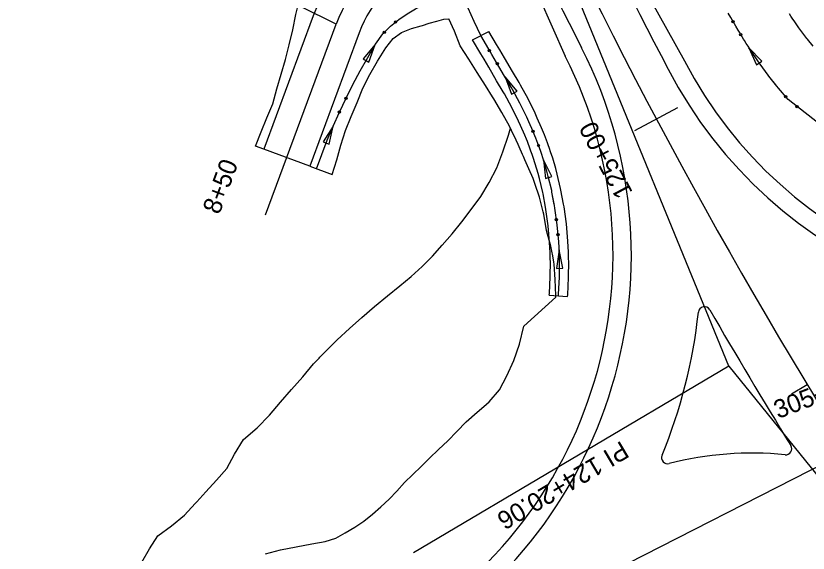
# Model space of a CAD drawing. Extents: x 916431 to 921570, y 1763982 to 1768032.
# Drawn here: x 918429.9 to 918689.4, y 1765529.8 to 1765705.9 of the extents above; entities that cross this region are included whole.
import ezdxf

# ---------------------------------------------------------------- set-up
doc = ezdxf.new("R2010")
doc.units = 0
for name, color, linetype in [('R_Conc Ditch Paving', 7, 'Continuous'), ('R_Horz Alg', 7, 'Continuous'), ('R_Horz Alg Annot', 7, 'Continuous'), ('R_Horz Alg Stationing', 7, 'Continuous'), ('R_Proposed Const Limits', 7, 'Continuous'), ('R_Proposed Road', 7, 'Continuous'), ('R_Shld', 7, 'Continuous'), ('R_Special Ditch', 7, 'Continuous')]:
    doc.layers.add(name, color=color, linetype=linetype)

msp = doc.modelspace()

# ---------------------------------------------------------------- linework, layer by layer
at = {"layer": 'R_Conc Ditch Paving'}
for p, q in [((918579.5, 1765697.99), (918584.83, 1765700.77)), ((918604.6, 1765614.37), (918610.58, 1765613.93))]:
    msp.add_line(p, q, dxfattribs=at)
for points in [[(918610.58, 1765613.93), (918610.63, 1765614.5), (918610.91, 1765620.14), (918610.95, 1765625.47), (918610.94, 1765626.18), (918610.88, 1765628.53), (918610.81, 1765630.12), (918610.7, 1765632.06), (918610.19, 1765637.75), (918609.43, 1765643.28), (918609.28, 1765644.19), (918608.43, 1765648.71), (918608.32, 1765649.24), (918607.19, 1765654.01), (918606.71, 1765655.79), (918605.71, 1765659.18), (918605.01, 1765661.35), (918604.64, 1765662.43), (918604.23, 1765663.59), (918604, 1765664.24), (918603.01, 1765666.83), (918602.68, 1765667.66), (918602.08, 1765669.14), (918600.67, 1765672.38), (918599.95, 1765673.95), (918597.65, 1765678.62), (918595.16, 1765683.19), (918594.72, 1765683.96), (918592.54, 1765687.66), (918589.94, 1765692.07), (918588.4, 1765694.68), (918587.34, 1765696.48), (918584.83, 1765700.77)], [(918604.6, 1765614.37), (918604.64, 1765614.88), (918604.91, 1765620.31), (918604.95, 1765625.45), (918604.94, 1765626.05), (918604.88, 1765628.32), (918604.82, 1765629.82), (918604.71, 1765631.62), (918604.23, 1765637.08), (918603.5, 1765642.39), (918603.38, 1765643.15), (918602.55, 1765647.53), (918602.46, 1765647.92), (918601.37, 1765652.53), (918600.93, 1765654.16), (918599.97, 1765657.41), (918599.31, 1765659.46), (918598.97, 1765660.46), (918598.58, 1765661.57), (918598.37, 1765662.15), (918597.42, 1765664.66), (918597.12, 1765665.42), (918596.55, 1765666.81), (918595.19, 1765669.94), (918594.53, 1765671.37), (918592.33, 1765675.86), (918589.93, 1765680.26), (918589.54, 1765680.94), (918587.37, 1765684.61), (918584.77, 1765689.02), (918583.23, 1765691.64), (918582.17, 1765693.44), (918579.5, 1765697.99)]]:
    msp.add_lwpolyline(points, dxfattribs=at)
at = {"layer": 'R_Horz Alg'}
for p, q in [((918511.69, 1765640.62), (918534.84, 1765703.08)), ((918519.58, 1765470.12), (918702.47, 1765563.28))]:
    msp.add_line(p, q, dxfattribs=at)
for centre, radius, start, end in [((920196.91, 1766498.5), 1762.95, 202.25028, 218.97694), ((918581.72, 1765685.7), 50, 115.128, 159.6685)]:
    msp.add_arc(centre, radius, start, end, dxfattribs=at)
at = {"layer": 'R_Horz Alg Annot'}
for q in [(918594.92, 1765758.39), (918777.08, 1765450.54)]:
    msp.add_line((918663.37, 1765591.08), q, dxfattribs=at)
for points in [[(918534.84, 1765703.08), (918418.4, 1765760.9)], [(918663.37, 1765591.08), (918560.09, 1765529.97)]]:
    msp.add_lwpolyline(points, dxfattribs=at)
at = {"layer": 'R_Horz Alg Stationing'}
for points in [[(918632.61, 1765668.31), (918646.74, 1765675.81)], [(918683.9, 1765581.99), (918689.03, 1765585.1)]]:
    msp.add_lwpolyline(points, dxfattribs=at)
at = {"layer": 'R_Proposed Const Limits'}
for points in [[(918514.09, 1765677.06), (918515.41, 1765681.9), (918516.85, 1765686.7), (918518.22, 1765691.52), (918519.47, 1765696.39), (918520.6, 1765701.31), (918521.6, 1765706.27), (918523.01, 1765712.12), (918525.2, 1765718.28), (918528.95, 1765723.6), (918533.35, 1765728.36), (918534.22, 1765729.16), (918538.32, 1765732.48), (918543.28, 1765736.48), (918548.72, 1765739.77), (918552.79, 1765742.46)], [(918691.02, 1765695.87), (918689.16, 1765698.2), (918688.96, 1765698.44), (918687.01, 1765701), (918686.32, 1765701.96), (918684.98, 1765703.88), (918684.14, 1765705.14), (918683.74, 1765705.77), (918683.29, 1765706.47)], [(918535.04, 1765658.63), (918536.3, 1765663.5), (918537.9, 1765668.24), (918539.75, 1765672.88), (918541.67, 1765677.51), (918543.52, 1765682.15), (918545.88, 1765686.61), (918548.38, 1765691.01), (918551.03, 1765695.37), (918553.5, 1765698.4), (918556.2, 1765700.41), (918559.5, 1765701.66), (918562.61, 1765702.56), (918563.09, 1765702.74), (918565.26, 1765703.45), (918567.76, 1765704.15), (918570.11, 1765704.72), (918571.75, 1765704.91)], [(918606.77, 1765613.7), (918606.74, 1765614.2), (918606.57, 1765619.48), (918606.22, 1765624.51), (918606.13, 1765625.12), (918605.77, 1765627.27), (918605.49, 1765628.7), (918605.11, 1765630.42), (918603.72, 1765635.52), (918602.79, 1765640.85), (918602.6, 1765641.67), (918601.53, 1765646), (918601.4, 1765646.45), (918599.92, 1765650.96), (918599.28, 1765652.57), (918597.93, 1765655.71), (918597.01, 1765657.7), (918596.57, 1765658.7), (918596.11, 1765659.81), (918595.87, 1765660.41), (918594.79, 1765662.91), (918594.44, 1765663.69), (918593.78, 1765665.1), (918592.28, 1765668.24), (918591.54, 1765669.71), (918589.1, 1765674.22), (918586.49, 1765678.64), (918586.04, 1765679.35), (918583.73, 1765682.99), (918580.97, 1765687.34), (918579.34, 1765689.92), (918578.21, 1765691.7), (918575.45, 1765696.05), (918573.52, 1765700.82), (918571.75, 1765704.91)], [(918511.14, 1765662.16), (918508.43, 1765663.16), (918510.31, 1765667.8), (918512.17, 1765672.44), (918514.09, 1765677.06)], [(918471.19, 1765526.9), (918473.67, 1765531.25), (918476.39, 1765535.48), (918480.92, 1765538.78), (918485.2, 1765542.21), (918488.68, 1765546.05), (918489.2, 1765546.62), (918492.19, 1765549.87), (918495.69, 1765553.7), (918499.06, 1765557.6), (918501.52, 1765562.27), (918504.46, 1765567.06), (918509, 1765570.91), (918512.98, 1765575), (918516.62, 1765579.24), (918520.23, 1765583.46), (918523.86, 1765587.63), (918527.44, 1765591.81), (918529.21, 1765593.73), (918529.5, 1765594.02), (918531.26, 1765595.78), (918535.17, 1765599.65), (918539.21, 1765603.37), (918543.26, 1765607.05), (918547.37, 1765610.63), (918551.59, 1765614.07), (918555.71, 1765617.35), (918559.38, 1765620.45), (918562.96, 1765623.75), (918566.35, 1765627.16), (918569.58, 1765630.75), (918572.79, 1765634.46), (918575.93, 1765638.35), (918579.05, 1765642.41), (918582.18, 1765646.63), (918584.97, 1765651.2), (918587.47, 1765656.08), (918589.4, 1765661.33), (918591.21, 1765666.81), (918591.85, 1765669.09)], [(918526.15, 1765656.6), (918533.51, 1765653.87), (918535.04, 1765658.63)], [(918511.65, 1765529.62), (918516.62, 1765530.88), (918521.73, 1765531.86), (918526.85, 1765532.82), (918531.21, 1765533.66), (918534.66, 1765534.76), (918537.8, 1765536.47), (918540.88, 1765538.32), (918543.87, 1765540.33), (918546.72, 1765542.56), (918549.47, 1765544.96), (918552.15, 1765547.45), (918554.73, 1765550.11), (918557.18, 1765552.92), (918559.87, 1765555.55), (918562.65, 1765558.18), (918565.42, 1765560.95), (918568.29, 1765563.75), (918571.35, 1765566.58), (918574.34, 1765569.64), (918577.44, 1765572.84), (918581.02, 1765576.02), (918583.2, 1765577.85), (918584.89, 1765579.37), (918588.31, 1765583.28), (918590.72, 1765587.9), (918592.99, 1765592.88), (918594.83, 1765598.32), (918596.29, 1765604.23), (918606.77, 1765613.7)]]:
    msp.add_lwpolyline(points, dxfattribs=at)
at = {"layer": 'R_Proposed Road'}
for p, q in [((918527.33, 1765705.86), (918511.14, 1765662.16)), ((918542.34, 1765700.3), (918526.15, 1765656.6)), ((918526.15, 1765656.6), (918511.14, 1765662.16))]:
    msp.add_line(p, q, dxfattribs=at)
for centre, radius, start, end in [((920196.91, 1766498.5), 1751.95, 202.25028, 207.5444), ((920196.91, 1766498.5), 1773.95, 202.25028, 206.91983), ((918581.72, 1765685.7), 58, 115.128, 159.6685), ((918581.72, 1765685.7), 42, 115.128, 159.6685), ((918481.44, 1765627.45), 150, 296.9928, 26.9198), ((918776.54, 1765757.7), 150, 207.5444, 288.1508), ((918655.41, 1765608.55), 2, 29.9991, 173.8014), ((918481.44, 1765627.45), 173, 337.7203, 353.8014), ((920196.91, 1766498.5), 1777.95, 209.99913, 211.66855), ((918681.99, 1765564.02), 2, 264.1852, 31.6686), ((918643.37, 1765561.1), 2, 157.7203, 284.4658), ((918670.85, 1765454.59), 108, 84.1852, 104.4658)]:
    msp.add_arc(centre, radius, start, end, dxfattribs=at)
at = {"layer": 'R_Shld'}
for p, q in [((918589.61, 1765738.44), (918609.83, 1765692.64)), ((918624.6, 1765734.85), (918648.86, 1765691.11))]:
    msp.add_line(p, q, dxfattribs=at)
for centre, start, end in [((918481.44, 1765627.45), 296.9928, 26.9198), ((918776.54, 1765757.7), 207.5444, 288.1508)]:
    msp.add_arc(centre, 144, start, end, dxfattribs=at)
at = {"layer": 'R_Special Ditch'}
for p, q in [((918547.6, 1765696.41), (918543.66, 1765691.77)), ((918545.48, 1765690.7), (918547.6, 1765696.41)), ((918669.95, 1765695.39), (918672.44, 1765689.83)), ((918674.19, 1765691.02), (918669.95, 1765695.39)), ((918543.66, 1765691.77), (918545.48, 1765690.7)), ((918672.44, 1765689.83), (918674.19, 1765691.02)), ((918590.13, 1765685.84), (918592.27, 1765680.14)), ((918594.09, 1765681.21), (918590.13, 1765685.84)), ((918592.27, 1765680.14), (918594.09, 1765681.21)), ((918533.85, 1765669.73), (918530.54, 1765664.62)), ((918532.48, 1765663.79), (918533.85, 1765669.73)), ((918530.54, 1765664.62), (918532.48, 1765663.79)), ((918602.73, 1765658.66), (918603.41, 1765652.6)), ((918605.44, 1765653.2), (918602.73, 1765658.66)), ((918603.41, 1765652.6), (918605.44, 1765653.2)), ((918607.86, 1765629.14), (918606.97, 1765623.12)), ((918609.08, 1765623.18), (918607.86, 1765629.14)), ((918606.97, 1765623.12), (918609.08, 1765623.18))]:
    msp.add_line(p, q, dxfattribs=at)
for points in [[(918528.43, 1765655.75), (918531.9, 1765665.13), (918533.85, 1765669.74), (918535.9, 1765674.31), (918538.06, 1765678.84), (918540.32, 1765683.34), (918542.68, 1765687.79), (918545.14, 1765692.21), (918547.71, 1765696.6), (918550.09, 1765699.93), (918552.63, 1765702.47), (918555.33, 1765704.65), (918558.08, 1765706.56), (918558.58, 1765706.87), (918560.85, 1765708.2), (918563.62, 1765709.61), (918566.39, 1765710.81), (918569.17, 1765711.82), (918573.65, 1765713.58)], [(918582.5, 1765698.8), (918582.17, 1765699.38), (918580.03, 1765704.02), (918578.01, 1765708.41), (918578.01, 1765708.41), (918578, 1765708.44), (918577.9, 1765708.66), (918576.19, 1765712.41)], [(918607.59, 1765614.15), (918607.63, 1765614.69), (918607.91, 1765620.22), (918607.95, 1765625.46), (918607.94, 1765626.12), (918607.88, 1765628.43), (918607.81, 1765629.97), (918607.7, 1765631.84), (918607.21, 1765637.41), (918606.47, 1765642.84), (918606.33, 1765643.67), (918605.49, 1765648.12), (918605.39, 1765648.58), (918604.28, 1765653.27), (918603.82, 1765654.97), (918602.84, 1765658.29), (918602.16, 1765660.4), (918601.8, 1765661.45), (918601.4, 1765662.58), (918601.18, 1765663.19), (918600.22, 1765665.74), (918599.9, 1765666.54), (918599.31, 1765667.98), (918597.93, 1765671.16), (918597.24, 1765672.66), (918594.99, 1765677.24), (918592.55, 1765681.73), (918592.13, 1765682.45), (918589.95, 1765686.14), (918587.35, 1765690.55), (918585.81, 1765693.16), (918584.76, 1765694.96), (918582.17, 1765699.38), (918580.03, 1765704.02), (918578.01, 1765708.41)], [(918701.52, 1765663.82), (918682.87, 1765678.39), (918679.63, 1765682.2), (918679.13, 1765682.8), (918676.54, 1765686.08), (918676.27, 1765686.43), (918673.6, 1765690.06), (918672.65, 1765691.42), (918670.81, 1765694.12), (918669.67, 1765695.88), (918669.11, 1765696.76), (918668.5, 1765697.74), (918668.18, 1765698.26), (918666.84, 1765700.49), (918666.43, 1765701.2), (918665.68, 1765702.48), (918664.01, 1765705.35), (918663.22, 1765706.72)], [(918582.52, 1765698.77), (918582.5, 1765698.8)], [(918540.31, 1765683.31), (918540.32, 1765683.34), (918542.68, 1765687.79), (918545.14, 1765692.21), (918547.6, 1765696.41)], [(918678.76, 1765683.26), (918676.54, 1765686.08), (918676.27, 1765686.43), (918673.6, 1765690.06), (918672.65, 1765691.42), (918670.81, 1765694.12), (918669.97, 1765695.41)], [(918597.25, 1765672.65), (918597.24, 1765672.66), (918594.99, 1765677.24), (918592.55, 1765681.73), (918592.13, 1765682.45), (918590.13, 1765685.84)], [(918540.29, 1765683.28), (918540.3, 1765683.31)], [(918678.79, 1765683.23), (918678.76, 1765683.26)], [(918597.27, 1765672.61), (918597.25, 1765672.65)], [(918528.43, 1765655.75), (918531.9, 1765665.13), (918533.85, 1765669.73)], [(918606.25, 1765644.09), (918605.49, 1765648.12), (918605.39, 1765648.58), (918604.28, 1765653.27), (918603.82, 1765654.97), (918602.84, 1765658.29), (918602.72, 1765658.65)], [(918606.26, 1765644.05), (918606.25, 1765644.09)], [(918607.59, 1765614.15), (918607.63, 1765614.69), (918607.91, 1765620.22), (918607.95, 1765625.46), (918607.94, 1765626.12), (918607.88, 1765628.43), (918607.85, 1765629.14)]]:
    msp.add_lwpolyline(points, dxfattribs=at)
for centre in [(918554.25, 1765703.83), (918664.77, 1765703.97), (918664.77, 1765703.97), (918550.56, 1765700.45), (918667.31, 1765699.65), (918585.01, 1765694.45), (918587.55, 1765690.14), (918538.02, 1765678.84), (918681.97, 1765679.4), (918685.73, 1765676.11), (918535.87, 1765674.31), (918599.24, 1765668.04), (918601.07, 1765663.38), (918606.94, 1765639.11), (918607.46, 1765634.13)]:
    msp.add_circle(centre, 0.375, dxfattribs=at)

# ---------------------------------------------------------------- texts
at = {"layer": 'R_Horz Alg Annot'}
msp.add_text('PI 124+20.06', height=6, rotation=210.6136, dxfattribs=at).set_placement((918628.21, 1765566.79))
at = {"layer": 'R_Horz Alg Stationing'}
for s, rotation, p in [('125+00', 117.9555, (918632.05, 1765648.03)), ('8+50', 69.6685, (918496.54, 1765640.5)), ('305+00', 21.0383, (918679.54, 1765573.75))]:
    msp.add_text(s, height=6, rotation=rotation, dxfattribs=at).set_placement(p)

doc.saveas('drawing.dxf')
